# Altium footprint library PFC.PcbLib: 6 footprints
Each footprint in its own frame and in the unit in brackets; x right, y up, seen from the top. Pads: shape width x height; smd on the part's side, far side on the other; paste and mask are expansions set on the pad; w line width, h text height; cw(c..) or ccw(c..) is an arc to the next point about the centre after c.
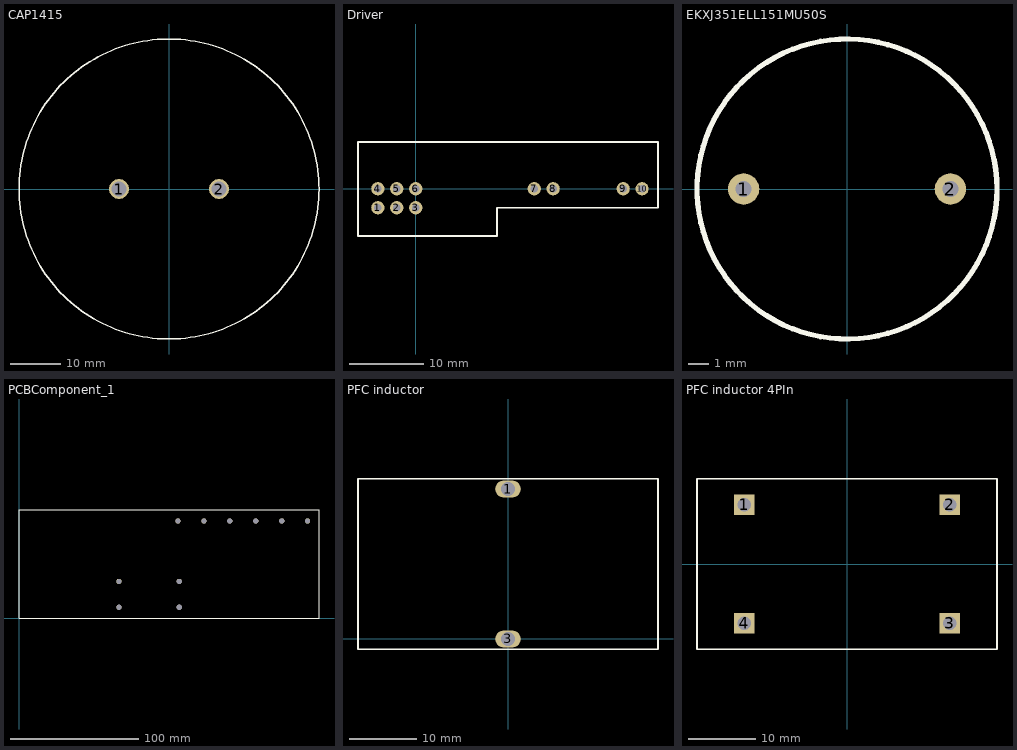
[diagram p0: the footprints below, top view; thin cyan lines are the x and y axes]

## CAP1415 [mm]
pads (2):
  round 4 hole 3: 1(-10,0) 2(10,0)
Top Overlay:
  circle w0.254: c0,0 r30
3D body: height 45, standoff 0, extent -29.999,-29.999 29.999,29.999

## Driver [mil]
pads (10):
  round 70 hole 40: 1(-200,-100) 2(-100,-100) 3(0,-100) 4(-200,0) 5(-100,0) 6(0,0) 7(626,0) 8(726,0) 9(1096,0) 10(1196,0)
Top Overlay:
  lines w10: -305,-250 430,-250 430,-100 1280,-100 1280,248.03 -305,248.03 -305,-250
3D body: height 1600, standoff 0, extent -299.21,-102.36 1275.59,244.09
3D body: height 1600, standoff 0, extent -297.24,-249.1 429.13,-86.61

## EKXJ351ELL151MU50S [mil] "150uF 350V"
height 1968.5
pads (2):
  round 60 hole 30: 1(-196.85,0) 2(196.85,0)
Top Overlay:
  circle w10: c0,0 r285.43
3D body: height 1968.5, standoff 0, extent -285.41,-285.41 285.41,285.41

## PCBComponent_1 [mil]
pads (10):
  round 160 hole 160: 1(3080,340) 1(3080,1140) 1(4900,3000) 1(4940,340) 1(4940,1140) 1(5700,3000) 1(6500,3000) 1(7300,3000) 1(8103.94,3003.94) 1(8900,3000)
Top Overlay:
  lines w20: 0,3346.46 0,0 9250,0 9250,3350 0,3350

## PFC inductor [mil]
height 1680
pads (2):
  oval 150x100 hole 80: 1(0,880) 3(0,0)
Top Overlay:
  lines w10: -880,-60 880,-60 880,940 -880,940 -880,-60
3D body: height 1680, standoff 0, extent -875,-59.06 877.95,935.58

## PFC inductor 4PIn [mm]
pads (4):
  rect 3.048x3.048 hole 2: 1(-15.3,8.85) 2(15.3,8.85) 3(15.3,-8.85) 4(-15.3,-8.85)
Top Overlay:
  lines w0.254: 22.352,-12.7 22.352,12.7 ; 22.352,-12.7 22.352,12.7 ; 22.352,-12.7 -22.352,-12.7 -22.352,12.7 22.352,12.7
3D body: height 42.67, standoff 0, extent -22.2,-12.6 22.3,12.6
